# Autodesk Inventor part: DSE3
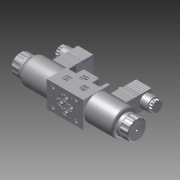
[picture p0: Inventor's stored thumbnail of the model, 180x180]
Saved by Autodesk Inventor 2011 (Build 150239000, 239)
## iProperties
Created: 2011-12
Part Number: DSE3
Document SubType Name: Modeling
Designer: khramov
Density: 1 g/cm^3
Author: khramov
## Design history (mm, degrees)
derived "DSE3_C08_11N_D24K1.iam"
node "Твердое тело1"
node "0144338.ipt:1"
node "190293_.ipt:1"
node "026977.ipt:1"
node "0119425_.ipt:1"
sketch "0670792_.ipt:1"
node "190293_.ipt:2"
node "026977.ipt:2"
node "0119425_.ipt:2"
sketch "0670792_.ipt:2"
sketch "3001630001_.ipt:1"
